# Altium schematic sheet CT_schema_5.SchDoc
size 405 x 321 mm
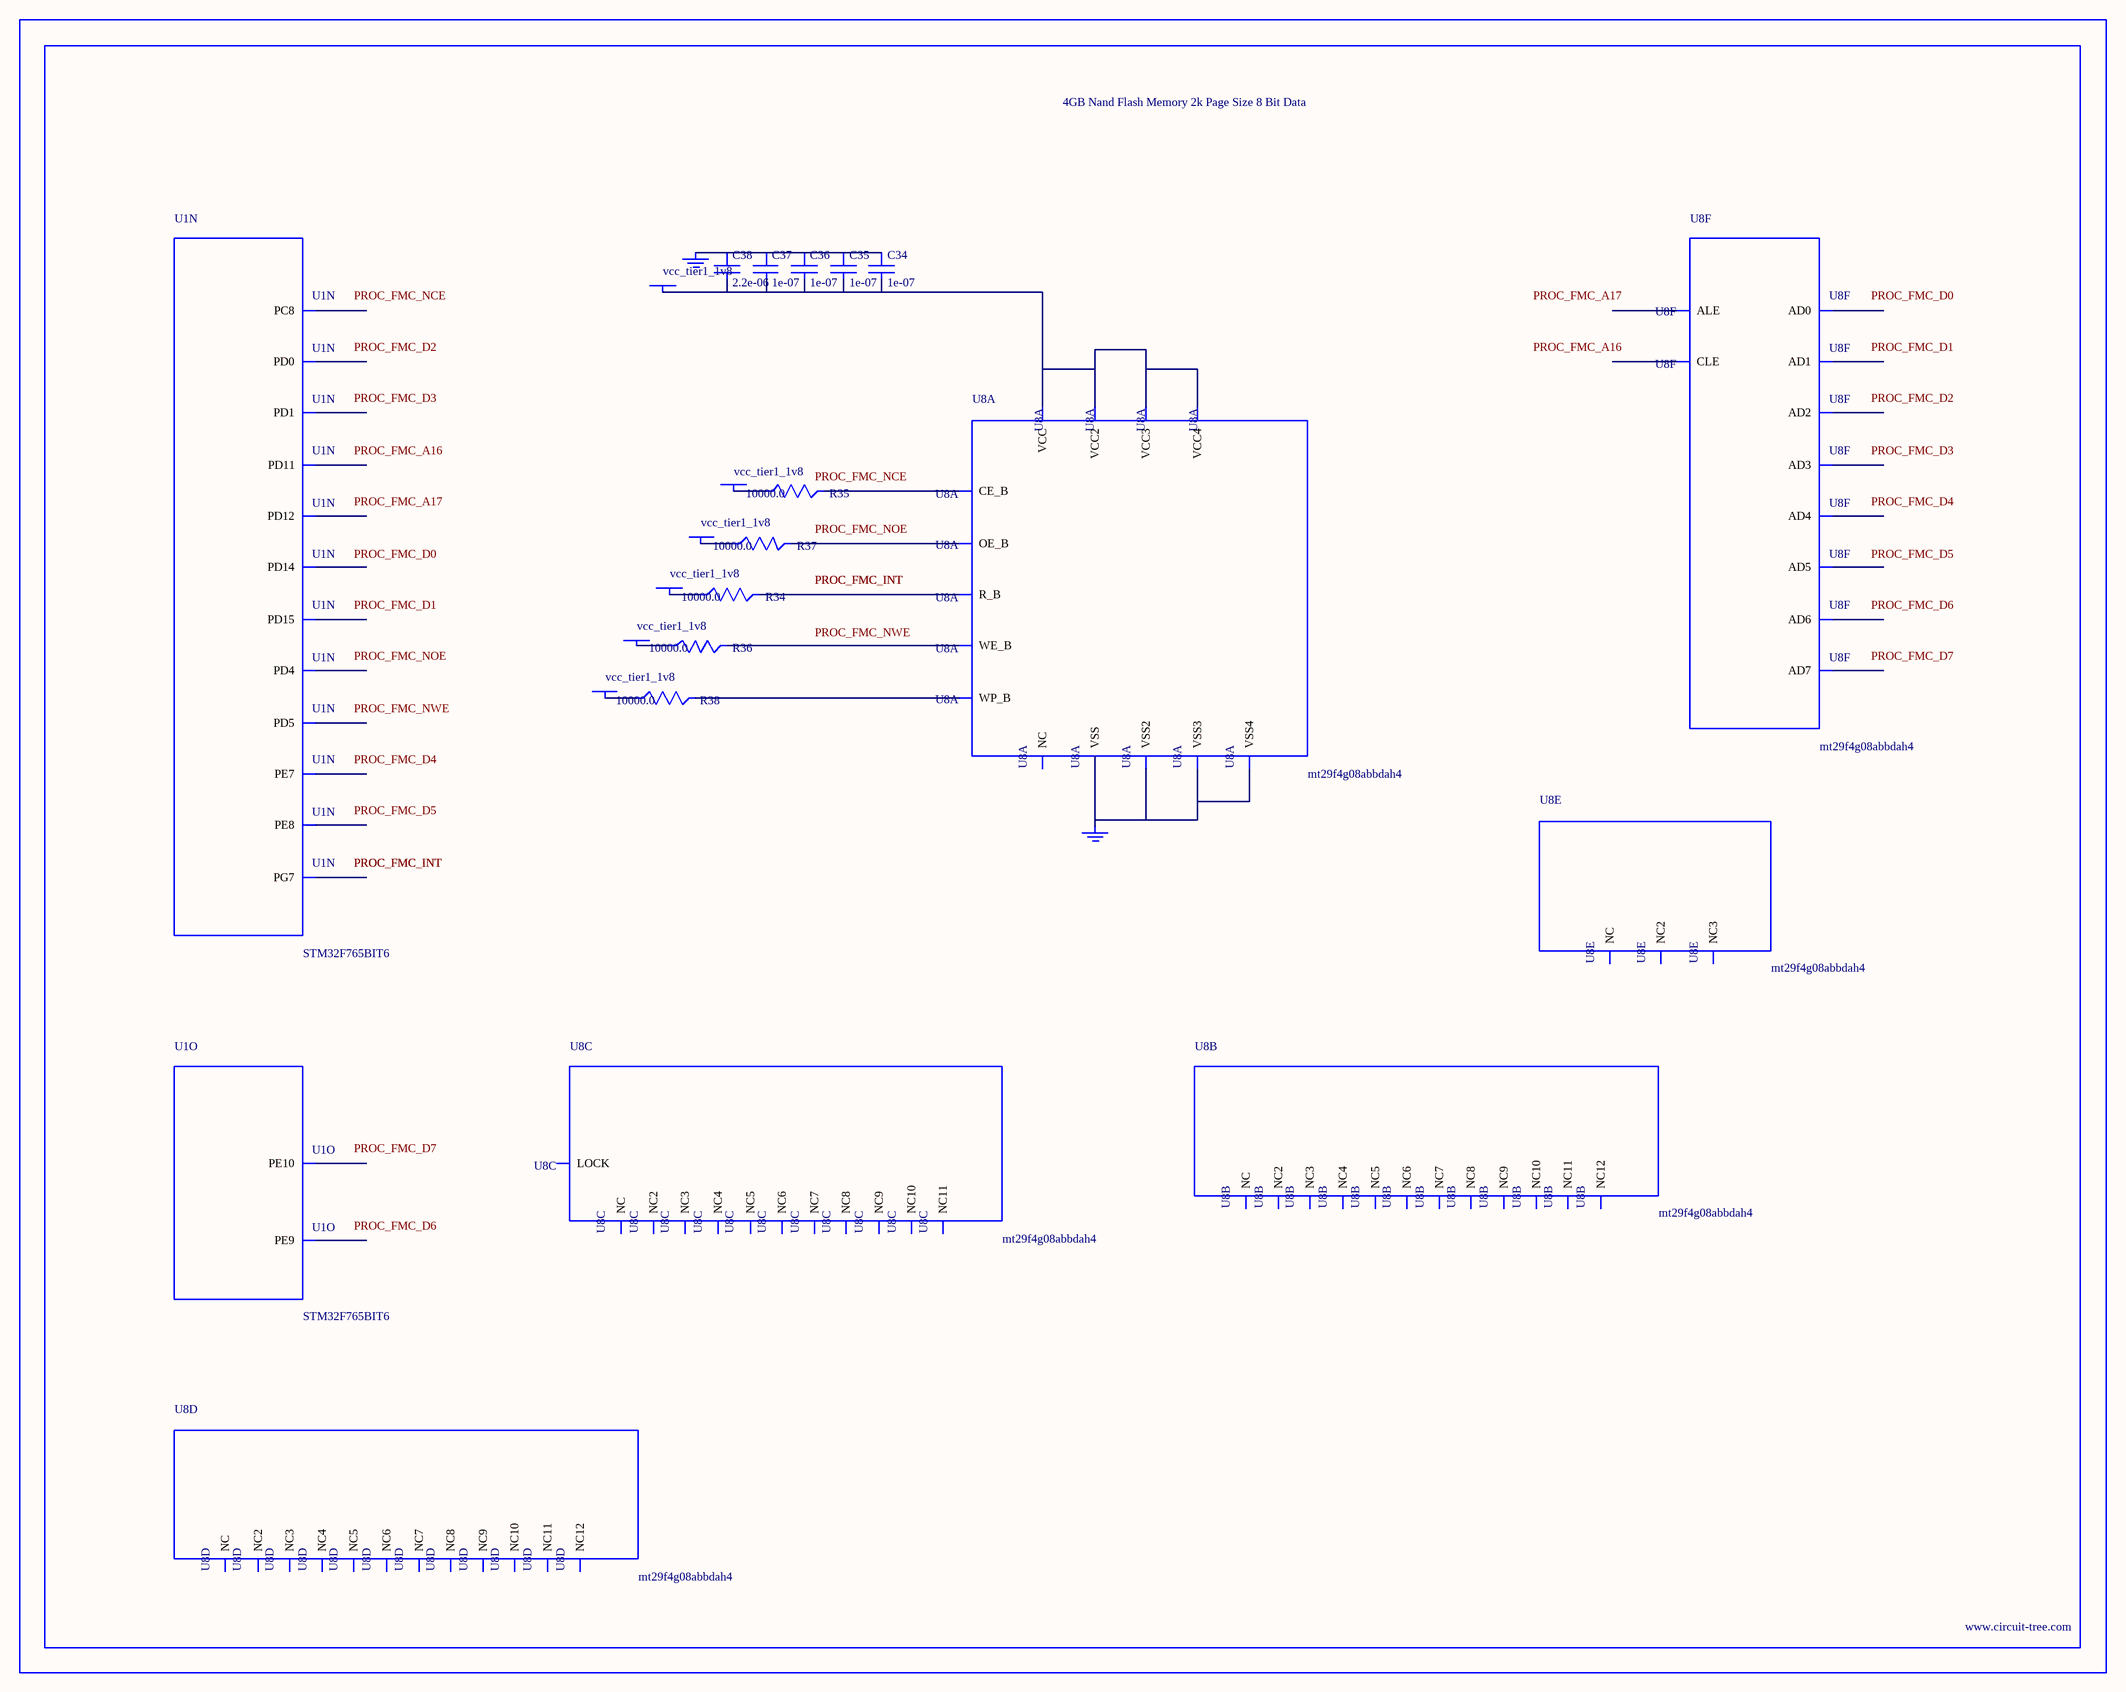
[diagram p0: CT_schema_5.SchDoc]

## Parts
BORDER4  (no value)
C34  1e-07  [C0402]
C35  1e-07  [C0402]
C36  1e-07  [C0402]
C37  1e-07  [C0402]
C38  2.2e-06  [C0603]
GND_INSTANCE_4_0  (no value)
GND_INSTANCE_4_1  (no value)
POWER_INSTANCE_4_0  vcc_tier1_1v8
POWER_INSTANCE_4_1  vcc_tier1_1v8
POWER_INSTANCE_4_2  vcc_tier1_1v8
POWER_INSTANCE_4_3  vcc_tier1_1v8
POWER_INSTANCE_4_4  vcc_tier1_1v8
POWER_INSTANCE_4_5  vcc_tier1_1v8
R34  10000.0  [R0603]
R35  10000.0  [R0603]
R36  10000.0  [R0603]
R37  10000.0  [R0603]
R38  10000.0  [R0603]
U1  STM32F765BIT6  [LQFP208]  (parts N,O of 17)
U8  mt29f4g08abbdah4  [VFBGA-63]  (parts A,B,C,D,E,F of 6)

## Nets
NetC34_1: C34.1 C35.1 C36.1 C37.1 C38.1 GND_INSTANCE_4_0.0(GND)
NetC34_2: C34.2 C35.2 C36.2 C37.2 C38.2 POWER_INSTANCE_4_0.0(PWR) U8.D3(VCC) U8.G4(VCC2) U8.H8(VCC3) U8.J6(VCC4)
NetGND_INSTANCE_4_1_0: GND_INSTANCE_4_1.0(GND) U8.C5(VSS) U8.F7(VSS2) U8.K3(VSS3) U8.K8(VSS4)
NetPOWER_INSTANCE_4_1_0: POWER_INSTANCE_4_1.0(PWR) R34.1
NetPOWER_INSTANCE_4_2_0: POWER_INSTANCE_4_2.0(PWR) R35.1
NetPOWER_INSTANCE_4_3_0: POWER_INSTANCE_4_3.0(PWR) R36.1
NetPOWER_INSTANCE_4_4_0: POWER_INSTANCE_4_4.0(PWR) R37.1
NetPOWER_INSTANCE_4_5_0: POWER_INSTANCE_4_5.0(PWR) R38.1
NetR34_2: R34.2 U8.C8(R_B)
NetR35_2: R35.2 U8.C6(CE_B)
NetR36_2: R36.2 U8.C7(WE_B)
NetR37_2: R37.2 U8.D4(OE_B)
NetR38_2: R38.2 U8.C3(WP_B)

Not connected (* = marked no-connect by the designer): U1 79(PE7) 80(PE8) 81(PE9) 84(PE10) 111(PD11) 112(PD12) 116(PD14) 117(PD15) 134(PG7) 140(PC8) 164(PD0) 165(PD1) 168(PD4) 169(PD5); U8 A1(NC) A2(NC3) A9(NC4) A10(NC2) B1(NC5) B9(NC7) B10(NC6) C4(ALE) D5(CLE) D6(NC8) D7(NC9) D8(NC10) E3(NC11) E4(NC12) E5(NC) E6(NC2) E7(NC3) E8(NC4) F3(NC5) F4(NC6) F5(NC7) F6(NC8) F8(NC9) G3(NC) G5(LOCK) G6(NC10) G7(NC11) G8(NC) H3(NC2) H4(AD0) H5(NC3) H6(NC4) H7(NC5) J3(NC6) J4(AD1) J5(NC7) J7(AD5) J8(AD7) K4(AD2) K5(AD3) K6(AD4) K7(AD6) L1(NC8) L2(NC10) L9(NC11) L10(NC9) M1(NC12) M2(NC2) M9(NC3) M10(NC)

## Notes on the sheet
- Labels drawn without touching a wire or pin: PROC_FMC_A16, PROC_FMC_A17, PROC_FMC_D0, PROC_FMC_D1, PROC_FMC_D2, PROC_FMC_D3, PROC_FMC_D4, PROC_FMC_D5, PROC_FMC_D6, PROC_FMC_D7, PROC_FMC_NCE, PROC_FMC_NOE, PROC_FMC_NWE

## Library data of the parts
BORDER4 = BORDER_PAGE4
C34-C37 = C0402C104K3RACTU
C38 = C0603C225K8RACTU
GND_INSTANCE_4_0 GND_INSTANCE_4_1 = GND
POWER_INSTANCE_4_0-POWER_INSTANCE_4_5 = PWR
R34-R38 = RC0603JR-0710KL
